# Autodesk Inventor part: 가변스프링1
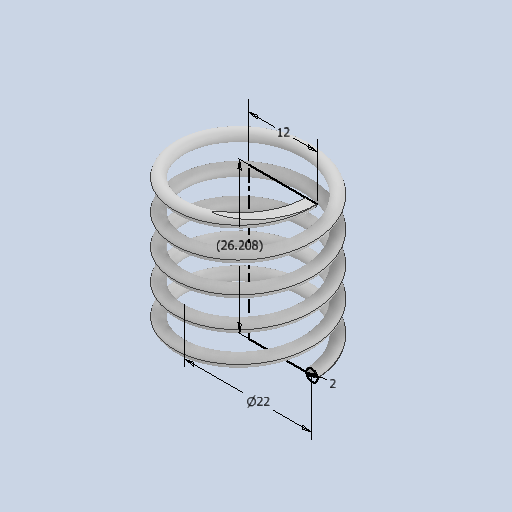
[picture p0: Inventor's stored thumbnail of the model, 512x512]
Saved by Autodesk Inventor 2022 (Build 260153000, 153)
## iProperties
Created: 2021-07
Part Number: 가변스프링1
Material: 일반
Document SubType Name: Modeling
Designer: micke
Density: 1 g/cm^3
Appearance: 기본값
Author: micke
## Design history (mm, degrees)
sketch "스케치1"
  geometry: L1 (0, 0)-(0, 26.208); L2 (0, 26.208)-(12, 26.208); L3 (0, 0)-(11, 0); C1 r 1 at (11, 0)
  constraints: 6 end point, 2 horizontal, 1 centre point, 1 coincident, 1 vertical
  dimensions: "d0" = 26.20829 distance of L1.start L1.end (derived); "d1" = 2 diameter of C1; "d2" = 22 diameter of L3.end L1; "d3" = 12 distance of L1.end L2.end
feature "코일1" sketch "스케치1" pitch "d4" = 10; turns "d6" = 5; dims "d5" = 26.20829 (= d0), "d7" = 0, angle "d8" = 90 deg, angle "d9" = 90 deg, "d10" = 0, "d11" = 0
sketch "스케치2"
  geometry: L1 (26.208, 12.5)-(0, 12.5); L2 (0, 12.5)-(0, -12.5); L3 (0, -12.5)-(26.208, -12.5); L4 (26.208, -12.5)-(26.208, 12.5); 2 further points
  constraints: 8 end point, 2 parallel, 1 coincident, 1 horizontal, 1 midpoint, 1 perpendicular
  dimensions: "d12" = 26.20829 distance of L1.start L1.end (= d0); "d13" = 25 distance of L3.end L1.start
extrude "돌출1" sketch "스케치2" extent not by distance; stored distance "d14" = 0; taper "d15" = 0 deg
node "솔리드1"
feature "A9D066F2-1C7D-4E18-AEED-F7BC21143FA4" dims "d4" = 10, "d5" = 26.20829 (= d0), "d6" = 50, "d7" = 0, "d8" = 90 deg, "d9" = 90 deg, "d10" = 0, "d11" = 0
